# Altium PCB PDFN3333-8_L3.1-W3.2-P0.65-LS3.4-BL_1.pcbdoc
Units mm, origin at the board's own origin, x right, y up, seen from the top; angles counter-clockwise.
Board outline 16.45 x 16.74 mm, 2 copper layers (Top Layer, Bottom Layer), stack 0 mm thick; 1 components, 0 nets, 5 pads, 0 vias.
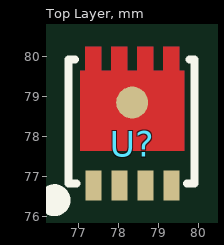
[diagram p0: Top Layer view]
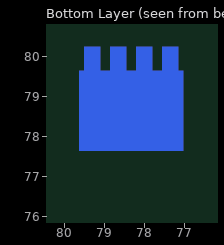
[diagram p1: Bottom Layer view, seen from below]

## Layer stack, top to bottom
Top Layer: signal copper (thickness not stored)
Bottom Layer: signal copper (thickness not stored)

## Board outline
86.296,69.85 69.85,69.85 69.85,86.59 86.296,86.59

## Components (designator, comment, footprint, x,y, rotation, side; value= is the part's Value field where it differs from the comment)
U? "" PDFN3333-8_L3.1-W3.2-P0.65-LS3.4-BL_1 78.346,77.857 r0 top

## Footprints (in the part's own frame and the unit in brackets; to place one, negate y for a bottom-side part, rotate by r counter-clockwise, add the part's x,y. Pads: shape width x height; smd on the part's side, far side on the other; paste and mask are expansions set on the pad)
PDFN3333-8_L3.1-W3.2-P0.65-LS3.4-BL_1 [mm]
  rect 0.4x0.75 smd: 1(-0.975,-1.083) 2(-0.325,-1.083) 3(0.325,-1.083) 4(0.975,-1.083)
  round 0.797 smd: 5(-0.004,0.986)
  Top Layer region: -0.775,1.783 -0.775,2.384 -1.175,2.384 -1.175,1.783 -1.305,1.783 -1.305,-0.217 1.295,-0.217 1.295,1.783 1.175,1.783 1.175,2.384 0.775,2.384 0.775,1.783 0.525,1.783 0.525,2.384 0.125,2.384 0.125,1.783 -0.125,1.783 -0.125,2.384 -0.525,2.384 -0.525,1.783
  Bottom Layer region: -0.775,1.783 -0.775,2.384 -1.175,2.384 -1.175,1.783 -1.305,1.783 -1.305,-0.217 1.295,-0.217 1.295,1.783 1.175,1.783 1.175,2.384 0.775,2.384 0.775,1.783 0.525,1.783 0.525,2.384 0.125,2.384 0.125,1.783 -0.125,1.783 -0.125,2.384 -0.525,2.384 -0.525,1.783
  Multi-Layer region: -0.775,1.783 -0.775,2.384 -1.175,2.384 -1.175,1.783 -1.305,1.783 -1.305,-0.217 1.295,-0.217 1.295,1.783 1.175,1.783 1.175,2.384 0.775,2.384 0.775,1.783 0.525,1.783 0.525,2.384 0.125,2.384 0.125,1.783 -0.125,1.783 -0.125,2.384 -0.525,2.384 -0.525,1.783
  silkscreen extent -2.15,-1.66 1.56,2.06

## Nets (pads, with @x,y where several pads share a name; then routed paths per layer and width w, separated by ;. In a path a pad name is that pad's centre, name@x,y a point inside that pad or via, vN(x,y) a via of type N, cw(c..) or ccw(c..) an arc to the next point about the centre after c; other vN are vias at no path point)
pads on no net: U?.1 U?.2 U?.3 U?.4 U?.5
